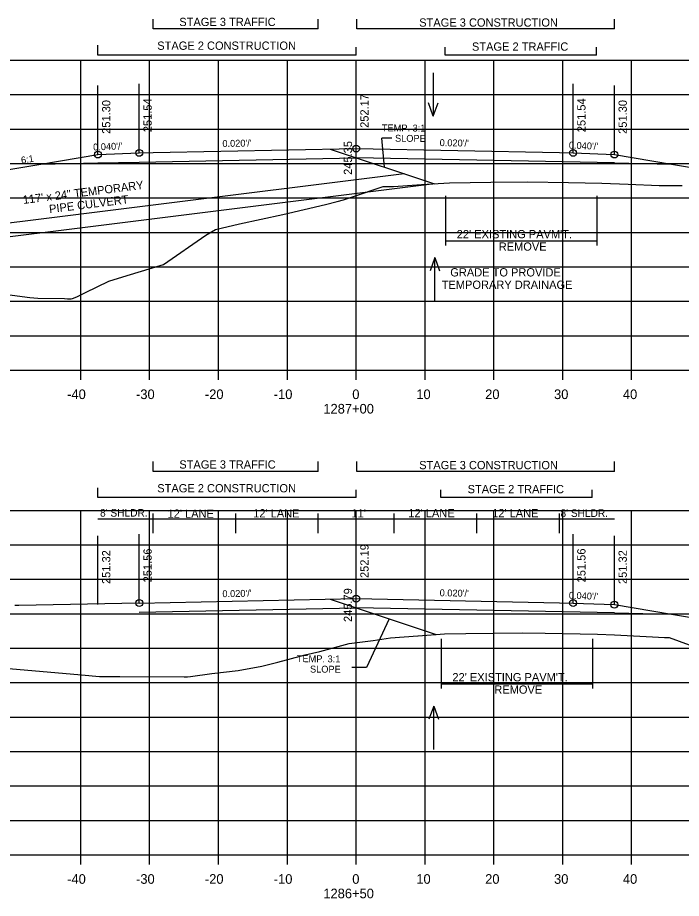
# Model space of a CAD drawing. Extents: x 1342547 to 1344156, y -1532351 to -1517216.
# Drawn here: x 1342653.7 to 1342750.1, y -1522097.2 to -1521969.4 of the extents above; entities that cross this region are included whole.
import ezdxf

# ---------------------------------------------------------------- set-up
doc = ezdxf.new("R2010")
doc.units = 0
for name, color, linetype in [('56', 7, 'Continuous'), ('R_Alt Surface', 7, 'Continuous'), ('R_Axis', 7, 'Continuous'), ('R_Axis Annot', 7, 'Continuous'), ('R_Draft', 7, 'Continuous'), ('R_Exist Surface', 7, 'Continuous'), ('R_Fin Surface', 7, 'Continuous'), ('R_Grid', 7, 'Continuous'), ('R_No Plot', 7, 'Continuous'), ('R_Water', 7, 'Continuous'), ('R_Xsect Elev', 7, 'Continuous'), ('R_Xsect Slope', 7, 'Continuous')]:
    doc.layers.add(name, color=color, linetype=linetype)

msp = doc.modelspace()

# ---------------------------------------------------------------- linework, layer by layer
at = {"layer": '56'}
msp.add_line((1342671.37, -1522054.37), (1342653.87, -1522054.72), dxfattribs=at)
msp.add_lwpolyline([(1342653.87, -1522054.72), (1342653.28, -1522054.73)], dxfattribs=at)
at = {"layer": 'R_Alt Surface'}
for points in [[(1342665.37, -1521990.48), (1342671.37, -1521990.36), (1342702.87, -1521989.73)], [(1342740.37, -1521990.48), (1342702.87, -1521989.73)], [(1342657.09, -1521990.65), (1342665.37, -1521990.48)], [(1342740.37, -1521990.48), (1342748.64, -1521990.65)], [(1342671.37, -1522055.7), (1342702.87, -1522055.07)], [(1342740.37, -1522055.82), (1342702.87, -1522055.07)], [(1342740.37, -1522055.82), (1342748.64, -1522055.99)]]:
    msp.add_lwpolyline(points, dxfattribs=at)
at = {"layer": 'R_Axis'}
for p, q in [((1342562.87, -1522020.57), (1342842.87, -1522020.57)), ((1342662.87, -1522021.97), (1342662.87, -1522020.57)), ((1342672.87, -1522021.97), (1342672.87, -1522020.57)), ((1342682.87, -1522021.97), (1342682.87, -1522020.57)), ((1342692.87, -1522021.97), (1342692.87, -1522020.57)), ((1342702.87, -1522021.97), (1342702.87, -1522020.57)), ((1342712.87, -1522021.97), (1342712.87, -1522020.57)), ((1342722.87, -1522021.97), (1342722.87, -1522020.57)), ((1342732.87, -1522021.97), (1342732.87, -1522020.57)), ((1342742.87, -1522021.97), (1342742.87, -1522020.57)), ((1342562.87, -1522090.93), (1342842.87, -1522090.93)), ((1342662.87, -1522092.33), (1342662.87, -1522090.93)), ((1342672.87, -1522092.33), (1342672.87, -1522090.93)), ((1342682.87, -1522092.33), (1342682.87, -1522090.93)), ((1342692.87, -1522092.33), (1342692.87, -1522090.93)), ((1342702.87, -1522092.33), (1342702.87, -1522090.93)), ((1342712.87, -1522092.33), (1342712.87, -1522090.93)), ((1342722.87, -1522092.33), (1342722.87, -1522090.93)), ((1342732.87, -1522092.33), (1342732.87, -1522090.93)), ((1342742.87, -1522092.33), (1342742.87, -1522090.93))]:
    msp.add_line(p, q, dxfattribs=at)
at = {"layer": 'R_Draft'}
for p, q in [((1342673.37, -1521971.03), (1342673.37, -1521969.6)), ((1342697.37, -1521971.03), (1342697.37, -1521969.6)), ((1342702.95, -1521971.03), (1342702.95, -1521969.6)), ((1342740.37, -1521971.03), (1342740.37, -1521969.6)), ((1342697.37, -1521971.03), (1342673.37, -1521971.03)), ((1342740.37, -1521971.03), (1342702.95, -1521971.03)), ((1342665.35, -1521974.83), (1342665.35, -1521973.4)), ((1342702.87, -1521974.83), (1342702.87, -1521973.68)), ((1342715.78, -1521974.83), (1342715.78, -1521973.68)), ((1342737.78, -1521974.83), (1342737.78, -1521973.68)), ((1342702.87, -1521974.83), (1342665.35, -1521974.83)), ((1342737.78, -1521974.83), (1342715.78, -1521974.83)), ((1342699.09, -1521988.47), (1342714.22, -1521993.52)), ((1342715.83, -1521995.27), (1342715.83, -1522002.47)), ((1342737.83, -1521995.27), (1342737.83, -1522002.47)), ((1342715.83, -1522001.8), (1342737.83, -1522001.8)), ((1342673.37, -1522035.27), (1342673.37, -1522033.84)), ((1342697.37, -1522035.27), (1342697.37, -1522033.84)), ((1342702.95, -1522035.27), (1342702.95, -1522033.84)), ((1342740.37, -1522035.27), (1342740.37, -1522033.84)), ((1342697.37, -1522035.27), (1342673.37, -1522035.27)), ((1342740.37, -1522035.27), (1342702.95, -1522035.27)), ((1342665.35, -1522039.07), (1342665.35, -1522037.64)), ((1342702.87, -1522039.07), (1342702.87, -1522037.93)), ((1342715.14, -1522039.07), (1342715.14, -1522037.93)), ((1342737.14, -1522039.07), (1342737.14, -1522037.93)), ((1342702.87, -1522039.07), (1342665.35, -1522039.07)), ((1342737.14, -1522039.07), (1342715.14, -1522039.07)), ((1342699.09, -1522053.81), (1342714.46, -1522058.94)), ((1342715.2, -1522059.58), (1342715.2, -1522066.78)), ((1342737.2, -1522059.58), (1342737.2, -1522066.78)), ((1342715.2, -1522066.11), (1342737.2, -1522066.11))]:
    msp.add_line(p, q, dxfattribs=at)
at = {"layer": 'R_Exist Surface'}
for points in [[(1342651.44, -1522009.47), (1342655.49, -1522010.03), (1342656.62, -1522010.11), (1342660.49, -1522010.17), (1342660.93, -1522010.24), (1342661.39, -1522010.24), (1342661.5, -1522010.2), (1342661.67, -1522010.18), (1342662.29, -1522009.94), (1342663.55, -1522009.31), (1342666.96, -1522007.65), (1342669.62, -1522006.82), (1342674.9, -1522005.24), (1342681.05, -1522000.97), (1342682.45, -1522000.17), (1342685.92, -1521999.35), (1342692.22, -1521998), (1342698.4, -1521996.54), (1342700.12, -1521996.1), (1342701.02, -1521995.83), (1342702.33, -1521995.4), (1342706.8, -1521993.93), (1342707.69, -1521993.91), (1342708.27, -1521993.92), (1342712.35, -1521993.64), (1342716.42, -1521993.37), (1342722.43, -1521993.29), (1342727.77, -1521993.22), (1342733.69, -1521993.33), (1342738.56, -1521993.42), (1342742.37, -1521993.57), (1342746.85, -1521993.76), (1342748.28, -1521993.76), (1342750.2, -1521993.76)], [(1342651.33, -1522063.78), (1342662.97, -1522064.82), (1342665.59, -1522065.03), (1342665.94, -1522065.05), (1342668.54, -1522065.06), (1342677.89, -1522065.08), (1342678.38, -1522065.08), (1342678.81, -1522065.04), (1342681.9, -1522064.62), (1342685.74, -1522064.16), (1342689.18, -1522063.56), (1342691.49, -1522062.98), (1342695.44, -1522061.87), (1342697.61, -1522061.42), (1342701.86, -1522060.26), (1342705.35, -1522059.82), (1342707.86, -1522059.42), (1342711.84, -1522059.12), (1342711.85, -1522059.12), (1342715.7, -1522058.85), (1342718.81, -1522058.81), (1342727.04, -1522058.69), (1342730.29, -1522058.75), (1342737.9, -1522058.9), (1342740.4, -1522059.01), (1342745.88, -1522059.27), (1342747.63, -1522059.36), (1342748.34, -1522059.38), (1342751.21, -1522060.43)]]:
    msp.add_lwpolyline(points, dxfattribs=at)
at = {"layer": 'R_Fin Surface'}
for points in [[(1342572.33, -1522007.9), (1342581.4, -1522010.92), (1342589.4, -1522010.92), (1342643.37, -1521992.93), (1342657.09, -1521990.65), (1342665.37, -1521989.27), (1342671.37, -1521989.03), (1342673.37, -1521988.99), (1342702.87, -1521988.4), (1342732.37, -1521988.99), (1342734.37, -1521989.03), (1342740.37, -1521989.27), (1342748.64, -1521990.65), (1342762.37, -1521992.93), (1342801.45, -1522005.96)], [(1342671.37, -1522054.37), (1342702.87, -1522053.74), (1342732.37, -1522054.33), (1342734.37, -1522054.37), (1342740.37, -1522054.61), (1342748.64, -1522055.99), (1342762.37, -1522058.28), (1342801.44, -1522071.3)]]:
    msp.add_lwpolyline(points, dxfattribs=at)
at = {"layer": 'R_Grid'}
for p, q in [((1342562.87, -1521975.57), (1342842.87, -1521975.57)), ((1342662.87, -1522020.57), (1342662.87, -1521975.57)), ((1342672.87, -1522020.57), (1342672.87, -1521975.57)), ((1342682.87, -1522020.57), (1342682.87, -1521975.57)), ((1342692.87, -1522020.57), (1342692.87, -1521975.57)), ((1342702.87, -1522020.57), (1342702.87, -1521975.57)), ((1342712.87, -1522020.57), (1342712.87, -1521975.57)), ((1342722.87, -1522020.57), (1342722.87, -1521975.57)), ((1342732.87, -1522020.57), (1342732.87, -1521975.57)), ((1342742.87, -1522020.57), (1342742.87, -1521975.57)), ((1342562.87, -1521980.57), (1342842.87, -1521980.57)), ((1342562.87, -1521985.57), (1342842.87, -1521985.57)), ((1342562.87, -1521990.57), (1342842.87, -1521990.57)), ((1342562.87, -1521995.57), (1342842.87, -1521995.57)), ((1342562.87, -1522000.57), (1342842.87, -1522000.57)), ((1342562.87, -1522005.57), (1342842.87, -1522005.57)), ((1342562.87, -1522010.57), (1342842.87, -1522010.57)), ((1342562.87, -1522015.57), (1342842.87, -1522015.57)), ((1342562.87, -1522020.57), (1342842.87, -1522020.57)), ((1342562.87, -1522040.93), (1342842.87, -1522040.93)), ((1342662.87, -1522090.93), (1342662.87, -1522040.93)), ((1342672.87, -1522090.93), (1342672.87, -1522040.93)), ((1342682.87, -1522090.93), (1342682.87, -1522040.93)), ((1342692.87, -1522090.93), (1342692.87, -1522040.93)), ((1342702.87, -1522090.93), (1342702.87, -1522040.93)), ((1342712.87, -1522090.93), (1342712.87, -1522040.93)), ((1342722.87, -1522090.93), (1342722.87, -1522040.93)), ((1342732.87, -1522090.93), (1342732.87, -1522040.93)), ((1342742.87, -1522090.93), (1342742.87, -1522040.93)), ((1342562.87, -1522045.93), (1342842.87, -1522045.93)), ((1342562.87, -1522050.93), (1342842.87, -1522050.93)), ((1342562.87, -1522055.93), (1342842.87, -1522055.93)), ((1342562.87, -1522060.93), (1342842.87, -1522060.93)), ((1342562.87, -1522065.93), (1342842.87, -1522065.93)), ((1342562.87, -1522070.93), (1342842.87, -1522070.93)), ((1342562.87, -1522075.93), (1342842.87, -1522075.93)), ((1342562.87, -1522080.93), (1342842.87, -1522080.93)), ((1342562.87, -1522085.93), (1342842.87, -1522085.93)), ((1342562.87, -1522090.93), (1342842.87, -1522090.93))]:
    msp.add_line(p, q, dxfattribs=at)
at = {"layer": 'R_No Plot'}
for centre in [(1342702.87, -1521988.4), (1342665.37, -1521989.27), (1342671.37, -1521989.03), (1342734.37, -1521989.03), (1342740.37, -1521989.27), (1342671.37, -1522054.37), (1342702.87, -1522053.74), (1342734.37, -1522054.37), (1342740.37, -1522054.61)]:
    msp.add_circle(centre, 0.5, dxfattribs=at)
at = {"layer": 'R_Water'}
for p, q in [((1342714.06, -1521977.39), (1342714.06, -1521983.68)), ((1342714.06, -1521983.68), (1342713.36, -1521981.76)), ((1342714.06, -1521983.68), (1342714.76, -1521981.76)), ((1342714.29, -1522004.24), (1342713.59, -1522006.16)), ((1342714.29, -1522010.52), (1342714.29, -1522004.24)), ((1342714.29, -1522004.24), (1342714.99, -1522006.16)), ((1342714.13, -1522069.33), (1342713.43, -1522071.25)), ((1342714.13, -1522075.61), (1342714.13, -1522069.33)), ((1342714.13, -1522069.33), (1342714.83, -1522071.25))]:
    msp.add_line(p, q, dxfattribs=at)
for points in [[(1342709.83, -1521992.05), (1342597.73, -1522006.08)], [(1342714.22, -1521993.52), (1342597.98, -1522008.06)]]:
    msp.add_lwpolyline(points, dxfattribs=at)
at = {"layer": 'R_Xsect Elev'}
for p, q in [((1342702.87, -1521988.4), (1342702.87, -1521978.4)), ((1342665.37, -1521989.27), (1342665.37, -1521979.27)), ((1342671.37, -1521989.03), (1342671.37, -1521979.03)), ((1342734.37, -1521989.03), (1342734.37, -1521979.03)), ((1342740.37, -1521989.27), (1342740.37, -1521979.27)), ((1342702.87, -1521995.22), (1342702.87, -1521985.22)), ((1342706.98, -1521991.11), (1342706.59, -1521986.92)), ((1342708.04, -1521986.92), (1342706.59, -1521986.92)), ((1342673.37, -1522044.22), (1342673.37, -1522041.36)), ((1342685.37, -1522044.22), (1342685.37, -1522041.36)), ((1342697.37, -1522044.22), (1342697.37, -1522041.36)), ((1342708.37, -1522044.22), (1342708.37, -1522041.36)), ((1342720.37, -1522044.22), (1342720.37, -1522041.36)), ((1342732.37, -1522044.22), (1342732.37, -1522041.36)), ((1342740.37, -1522042.22), (1342665.37, -1522042.22)), ((1342702.87, -1522053.74), (1342702.87, -1522043.74)), ((1342665.37, -1522054.61), (1342665.37, -1522044.61)), ((1342671.37, -1522054.37), (1342671.37, -1522044.37)), ((1342734.37, -1522054.37), (1342734.37, -1522044.37)), ((1342740.37, -1522054.61), (1342740.37, -1522044.61)), ((1342702.87, -1522060.13), (1342702.87, -1522050.13)), ((1342707.67, -1522056.67), (1342704.36, -1522063.75)), ((1342704.36, -1522063.75), (1342702.22, -1522063.75))]:
    msp.add_line(p, q, dxfattribs=at)

# ---------------------------------------------------------------- texts
at = {"layer": 'R_Axis Annot'}
for s, p in [('-40', (1342660.9, -1522024.77)), ('-30', (1342670.9, -1522024.77)), ('-20', (1342680.9, -1522024.77)), ('-10', (1342690.9, -1522024.77)), ('0', (1342702.3, -1522024.77)), ('10', (1342711.6, -1522024.77)), ('20', (1342721.6, -1522024.77)), ('30', (1342731.6, -1522024.77)), ('40', (1342741.6, -1522024.77)), ('1287+00', (1342698.1, -1522026.87)), ('-40', (1342660.9, -1522095.13)), ('-30', (1342670.9, -1522095.13)), ('-20', (1342680.9, -1522095.13)), ('-10', (1342690.9, -1522095.13)), ('0', (1342702.3, -1522095.13)), ('10', (1342711.6, -1522095.13)), ('20', (1342721.6, -1522095.13)), ('30', (1342731.6, -1522095.13)), ('40', (1342741.6, -1522095.13)), ('1286+50', (1342698.1, -1522097.23))]:
    msp.add_text(s, height=1.4, dxfattribs=at).set_placement(p)
at = {"layer": 'R_Draft'}
for s, p in [('STAGE 3 TRAFFIC', (1342677.18, -1521970.62)), ('STAGE 3 CONSTRUCTION', (1342712.02, -1521970.71)), ('STAGE 2 CONSTRUCTION', (1342673.98, -1521974.07)), ('STAGE 2 TRAFFIC', (1342719.68, -1521974.2)), ("22' EXISTING PAVM'T.", (1342717.47, -1522001.43)), ('REMOVE', (1342723.57, -1522003.23)), ('STAGE 3 TRAFFIC', (1342677.18, -1522034.86)), ('STAGE 3 CONSTRUCTION', (1342712.02, -1522034.95)), ('STAGE 2 CONSTRUCTION', (1342673.98, -1522038.31)), ('STAGE 2 TRAFFIC', (1342719.05, -1522038.44)), ("22' EXISTING PAVM'T.", (1342716.84, -1522065.74)), ('REMOVE', (1342722.93, -1522067.54))]:
    msp.add_text(s, height=1.2, dxfattribs=at).set_placement(p)
at = {"layer": 'R_Water'}
for s, rotation, p in [('117\' x 24" TEMPORARY', 7.1524, (1342654.54, -1521996.45)), ('PIPE CULVERT', 7.1524, (1342658.35, -1521997.79)), ('GRADE TO PROVIDE', 359.9909, (1342716.53, -1522006.97)), ('TEMPORARY DRAINAGE', 359.9909, (1342715.29, -1522008.77))]:
    msp.add_text(s, height=1.2, rotation=rotation, dxfattribs=at).set_placement(p)
at = {"layer": 'R_Xsect Elev'}
for s, p in [('251.30', (1342667.17, -1521986.27)), ('251.54', (1342673.17, -1521986.03)), ('252.17', (1342704.67, -1521985.4)), ('251.54', (1342736.17, -1521986.03)), ('251.30', (1342742.17, -1521986.27)), ('245.35', (1342702.27, -1521992.22)), ('251.56', (1342673.17, -1522051.37)), ('252.19', (1342704.67, -1522050.74)), ('251.56', (1342736.17, -1522051.37)), ('251.32', (1342667.17, -1522051.61)), ('251.32', (1342742.17, -1522051.61)), ('245.79', (1342702.27, -1522057.13))]:
    msp.add_text(s, height=1.2, rotation=90, dxfattribs=at).set_placement(p)
for s, height, p in [("8' SHLDR.", 1.1, (1342665.67, -1522041.83)), ("12' LANE", 1.2, (1342675.48, -1522042)), ("12' LANE", 1.2, (1342687.91, -1522041.95)), ("11'", 1.2, (1342702.18, -1522041.95)), ("12' LANE", 1.2, (1342710.44, -1522041.92)), ("12' LANE", 1.2, (1342722.61, -1522041.93)), ("8' SHLDR.", 1.1, (1342732.54, -1522041.87))]:
    msp.add_text(s, height=height, dxfattribs=at).set_placement(p)
at = {"layer": 'R_Xsect Slope'}
for s, rotation, p in [('TEMP. 3:1', 359.6242, (1342706.6, -1521985.9)), ('SLOPE', 359.6242, (1342708.51, -1521987.41)), ("0.040'/'", 2.2906, (1342664.69, -1521988.69)), ("0.020'/'", 1.1458, (1342683.45, -1521988.18)), ("0.020'/'", 358.8542, (1342714.98, -1521988.04)), ("0.040'/'", 357.7079, (1342733.74, -1521988.4)), ('6:1', 9.4623, (1342654.28, -1521990.61)), ("0.020'/'", 1.1458, (1342683.45, -1522053.53)), ("0.020'/'", 358.8542, (1342714.98, -1522053.38)), ("0.040'/'", 357.7079, (1342733.74, -1522053.74)), ('TEMP. 3:1', 359.6242, (1342694.25, -1522062.95)), ('SLOPE', 359.6242, (1342696.16, -1522064.46))]:
    msp.add_text(s, height=1, rotation=rotation, dxfattribs=at).set_placement(p)

doc.saveas('drawing.dxf')
